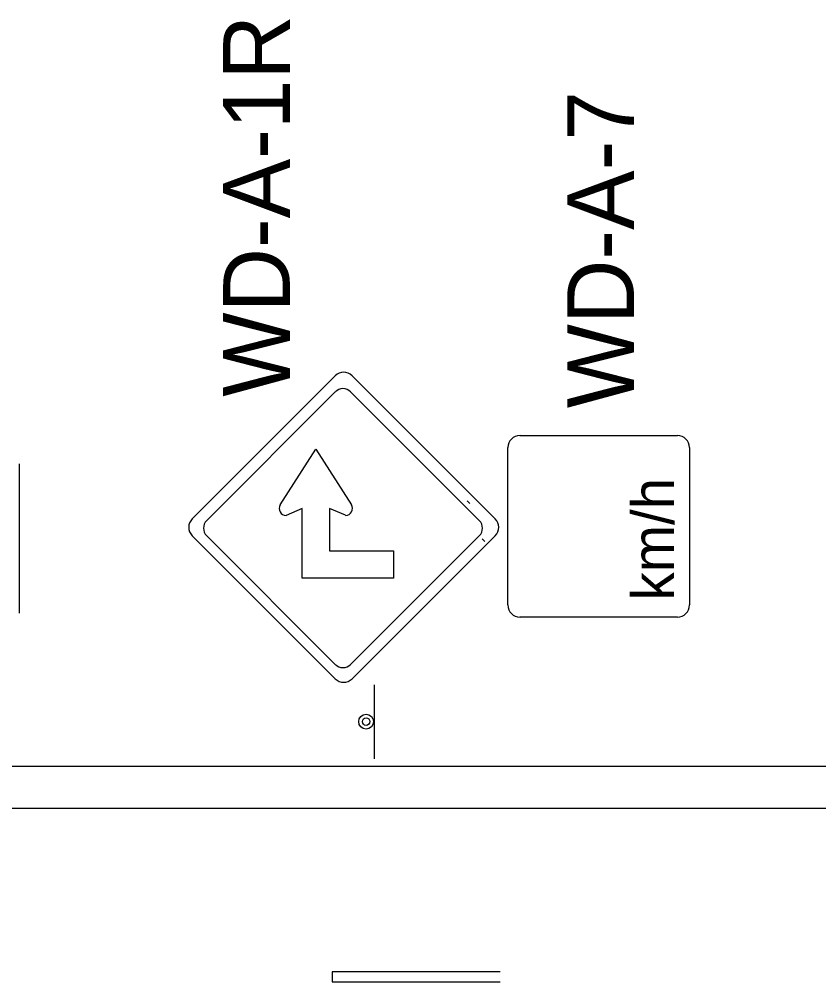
# Model space of a CAD drawing. Extents: x 1806 to 2022, y 110 to 389.
# Drawn here: x 1914.62 to 1937.63, y 284.05 to 311.75 of the extents above; entities that cross this region are included whole.
import ezdxf

# ---------------------------------------------------------------- set-up
doc = ezdxf.new("R2010")
doc.units = 0
for name, color, linetype in [('Level 10', 7, 'Continuous'), ('Level 2', 7, 'Continuous'), ('Level 44', 7, 'Continuous'), ('Level 50', 7, 'Continuous')]:
    doc.layers.add(name, color=color, linetype=linetype)

msp = doc.modelspace()

# ---------------------------------------------------------------- linework, layer by layer
at = {"layer": 'Level 10'}
for p, q in [((1957.331, 290.244), (1895.86, 290.244)), ((1957.331, 289.035), (1895.86, 289.035))]:
    msp.add_line(p, q, dxfattribs=at)
at = {"layer": 'Level 2'}
for p, q in [((1927.515, 297.897), (1927.593, 297.819)), ((1927.94, 296.804), (1928.018, 296.726)), ((1928.463, 284.342), (1923.625, 284.342)), ((1923.625, 284.342), (1923.625, 284.052)), ((1923.625, 284.052), (1928.463, 284.052))]:
    msp.add_line(p, q, dxfattribs=at)
at = {"layer": 'Level 44'}
for p, q in [((1923.715, 301.491), (1919.601, 297.377)), ((1928.321, 297.377), (1924.203, 301.491)), ((1920.015, 297.329), (1923.718, 301.032)), ((1924.158, 301.032), (1927.863, 297.329)), ((1929.033, 299.774), (1933.563, 299.774)), ((1922.134, 297.776), (1923.159, 299.384)), ((1923.159, 299.384), (1924.181, 297.779)), ((1928.684, 294.896), (1928.684, 299.424)), ((1933.912, 299.424), (1933.912, 294.896)), ((1914.62, 298.956), (1914.62, 294.665)), ((1922.759, 297.672), (1922.301, 297.471)), ((1922.759, 295.667), (1922.759, 297.672)), ((1924.013, 297.477), (1923.55, 297.675)), ((1923.55, 297.675), (1923.55, 296.458)), ((1919.601, 296.891), (1923.715, 292.77)), ((1923.718, 293.183), (1920.015, 296.891)), ((1927.863, 296.891), (1924.158, 293.183)), ((1924.203, 292.77), (1928.321, 296.891)), ((1923.55, 296.458), (1925.394, 296.458)), ((1925.394, 296.458), (1925.394, 295.667)), ((1925.394, 295.667), (1922.759, 295.667)), ((1933.563, 294.546), (1929.033, 294.546)), ((1933.564, 294.546), (1933.563, 294.546)), ((1924.203, 292.774), (1924.203, 292.77)), ((1924.842, 290.468), (1924.842, 292.601))]:
    msp.add_line(p, q, dxfattribs=at)
msp.add_lwpolyline([(1914.624, 295.459), (1914.624, 295.531)], dxfattribs=at)
for radius in [0.213, 0.107]:
    msp.add_circle((1924.604, 291.539), radius, dxfattribs=at)
for centre, radius, start, end in [((1923.959, 301.25), 0.345, 45, 135), ((1923.938, 300.814), 0.31, 45, 135), ((1929.035, 299.425), 0.349, 90, 180), ((1933.564, 299.425), 0.349, 360, 90), ((1922.301, 297.67), 0.198, 147.5038, 270.1058), ((1924.014, 297.674), 0.198, 270.1051, 32.4986), ((1919.843, 297.133), 0.345, 135, 225), ((1920.234, 297.109), 0.31, 135, 225), ((1927.643, 297.109), 0.31, 315, 45), ((1928.075, 297.133), 0.345, 315, 45), ((1929.035, 294.896), 0.349, 180, 270), ((1933.564, 294.896), 0.349, 270, 360), ((1923.938, 293.404), 0.31, 225, 315), ((1923.959, 293.017), 0.345, 225, 315)]:
    msp.add_arc(centre, radius, start, end, dxfattribs=at)

# ---------------------------------------------------------------- texts
msp.add_text('km/h', height=1.218, rotation=90, dxfattribs=at).set_placement((1933.47, 295.026))
at = {"layer": 'Level 50'}
for s, height, p in [('WD-A-1R', 1.9199, (1922.409, 300.892)), ('WD-A-7', 1.92, (1932.313, 300.559))]:
    msp.add_text(s, height=height, rotation=90, dxfattribs=at).set_placement(p)

doc.saveas('drawing.dxf')
